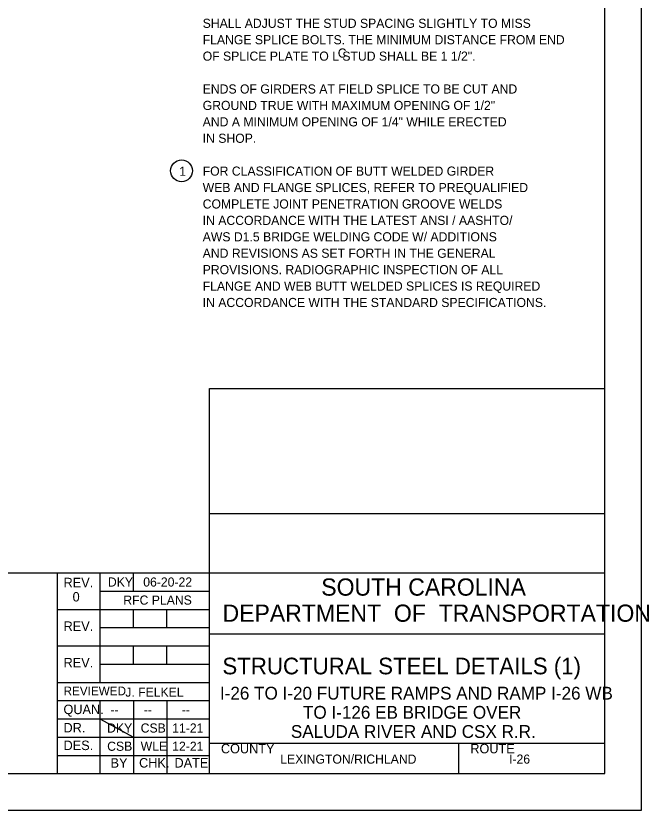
# Model space of a CAD drawing. Extents: x -448.1 to -400, y -140.7 to -111.4.
# Drawn here: x -411.56 to -399.99, y -140.7 to -126.19 of the extents above; entities that cross this region are included whole.
import ezdxf

# ---------------------------------------------------------------- set-up
doc = ezdxf.new("R2010")
doc.units = 0
for name, color, linetype in [('BR_BORDER LINES', 7, 'Continuous'), ('BR_TEXT', 7, 'Continuous'), ('Level 31', 7, 'Continuous')]:
    doc.layers.add(name, color=color, linetype=linetype)

msp = doc.modelspace()

# ---------------------------------------------------------------- linework, layer by layer
at = {"layer": 'BR_BORDER LINES'}
for p, q in [((-400.801, -140.031), (-400.801, -112.031)), ((-408.023, -140.031), (-408.023, -132.995)), ((-408.023, -132.995), (-400.801, -132.995)), ((-408.023, -135.282), (-400.801, -135.282)), ((-417.955, -136.364), (-410.801, -136.364)), ((-410.801, -140.031), (-410.801, -136.364)), ((-410.801, -136.364), (-400.801, -136.364)), ((-410.024, -136.364), (-410.024, -138.364)), ((-409.412, -136.697), (-409.412, -136.364)), ((-410.024, -136.697), (-408.023, -136.697)), ((-410.801, -137.031), (-408.023, -137.031)), ((-409.412, -137.364), (-409.412, -137.031)), ((-408.801, -137.364), (-408.801, -137.031)), ((-410.024, -137.364), (-408.023, -137.364)), ((-408.023, -137.475), (-408.023, -137.475)), ((-408.023, -137.475), (-400.801, -137.475)), ((-410.801, -137.698), (-408.023, -137.698)), ((-409.412, -138.031), (-409.412, -137.698)), ((-408.801, -138.031), (-408.801, -137.698)), ((-410.024, -138.031), (-408.023, -138.031)), ((-410.801, -138.364), (-408.023, -138.364)), ((-410.801, -138.698), (-408.023, -138.698)), ((-410.024, -138.698), (-410.024, -140.031)), ((-409.412, -138.698), (-409.412, -140.031)), ((-408.801, -138.698), (-408.801, -140.031)), ((-410.801, -139.031), (-408.023, -139.031)), ((-410.801, -139.364), (-408.023, -139.364)), ((-408.023, -139.475), (-400.801, -139.475)), ((-407.893, -139.475), (-400.801, -139.475)), ((-403.468, -140.031), (-403.468, -139.475)), ((-410.801, -139.698), (-408.023, -139.698)), ((-445.689, -140.031), (-400.801, -140.031))]:
    msp.add_line(p, q, dxfattribs=at)
at = {"layer": 'BR_TEXT'}
msp.add_circle((-408.533, -129.019), 0.2, dxfattribs=at)
at = {"layer": 'Level 31'}
for p, q in [((-404.412, -138.062), (-404.412, -138.062)), ((-410.024, -139.031), (-409.412, -139.364))]:
    msp.add_line(p, q, dxfattribs=at)
msp.add_lwpolyline([(-448.133, -140.698), (-400.133, -140.698), (-400.133, -111.364), (-448.133, -111.364)], close=True, dxfattribs=at)

# ---------------------------------------------------------------- texts
at = {"layer": 'BR_TEXT'}
for s, height, p in [('SHALL ADJUST THE STUD SPACING SLIGHTLY TO MISS', 0.16667, (-408.147, -126.408)), ('FLANGE SPLICE BOLTS. THE MINIMUM DISTANCE FROM END', 0.16667, (-408.147, -126.708)), ('C', 0.167, (-405.679, -126.952)), ('OF SPLICE PLATE TO L STUD SHALL BE 1 1/2".', 0.16667, (-408.147, -127.008)), ('ENDS OF GIRDERS AT FIELD SPLICE TO BE CUT AND', 0.16667, (-408.147, -127.608)), ('GROUND TRUE WITH MAXIMUM OPENING OF 1/2"', 0.16667, (-408.147, -127.908)), ('AND A MINIMUM OPENING OF 1/4" WHILE ERECTED', 0.16667, (-408.147, -128.208)), ('IN SHOP.', 0.1667, (-408.147, -128.508)), ('1', 0.167, (-408.575, -129.111)), ('FOR CLASSIFICATION OF BUTT WELDED GIRDER', 0.16667, (-408.147, -129.108)), ('WEB AND FLANGE SPLICES, REFER TO PREQUALIFIED', 0.16667, (-408.147, -129.408)), ('COMPLETE JOINT PENETRATION GROOVE WELDS', 0.16667, (-408.147, -129.708)), ('IN ACCORDANCE WITH THE LATEST ANSI / AASHTO/', 0.16667, (-408.147, -130.008)), ('AWS D1.5 BRIDGE WELDING CODE W/ ADDITIONS', 0.16667, (-408.147, -130.308)), ('AND REVISIONS AS SET FORTH IN THE GENERAL', 0.16667, (-408.147, -130.608)), ('PROVISIONS. RADIOGRAPHIC INSPECTION OF ALL', 0.16667, (-408.147, -130.908)), ('FLANGE AND WEB BUTT WELDED SPLICES IS REQUIRED', 0.16667, (-408.147, -131.208)), ('IN ACCORDANCE WITH THE STANDARD SPECIFICATIONS.', 0.16667, (-408.147, -131.508)), ('REV.', 0.1733, (-410.688, -136.627)), ('DKY', 0.1667, (-409.879, -136.614)), ('06-20-22', 0.1667, (-409.233, -136.614)), ('SOUTH CAROLINA', 0.31449, (-405.981, -136.78)), ('0', 0.173, (-410.523, -136.887)), ('RFC PLANS', 0.1667, (-409.597, -136.944)), ('DEPARTMENT  OF  TRANSPORTATION', 0.31449, (-407.785, -137.257)), ('REV.', 0.1733, (-410.688, -137.424)), ('REV.', 0.1733, (-410.688, -138.09)), ('STRUCTURAL STEEL DETAILS (1)', 0.304, (-407.787, -138.217)), ('REVIEWED', 0.16, (-410.689, -138.6)), ('J. FELKEL', 0.1667, (-409.561, -138.625)), ('I-26 TO I-20 FUTURE RAMPS AND RAMP I-26 WB', 0.23333, (-407.832, -138.678)), ('QUAN.', 0.1733, (-410.69, -138.944)), ('TO I-126 EB BRIDGE OVER', 0.23333, (-406.315, -139.028)), ('--', 0.1667, (-409.833, -138.948)), ('--', 0.1667, (-409.222, -138.948)), ('--', 0.1667, (-408.528, -138.948)), ('DR.', 0.1733, (-410.69, -139.279)), ('DKY', 0.1667, (-409.893, -139.281)), ('CSB', 0.1667, (-409.28, -139.281)), ('11-21', 0.1667, (-408.704, -139.281)), ('SALUDA RIVER AND CSX R.R.', 0.23333, (-406.536, -139.378)), ('DES.', 0.1733, (-410.688, -139.601)), ('CSB', 0.1667, (-409.892, -139.614)), ('WLE', 0.1667, (-409.28, -139.614)), ('12-21', 0.1667, (-408.704, -139.614)), ('COUNTY', 0.1733, (-407.814, -139.66)), ('ROUTE', 0.1733, (-403.258, -139.66)), ('LEXINGTON/RICHLAND', 0.16666, (-406.731, -139.849)), ('I-26', 0.1667, (-402.55, -139.849)), ('BY', 0.1733, (-409.83, -139.922)), ('CHK.', 0.1733, (-409.309, -139.92)), ('DATE', 0.1733, (-408.662, -139.92))]:
    msp.add_text(s, height=height, dxfattribs=at).set_placement(p)

doc.saveas('drawing.dxf')
